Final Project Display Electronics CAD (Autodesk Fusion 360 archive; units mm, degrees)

design "PCB"
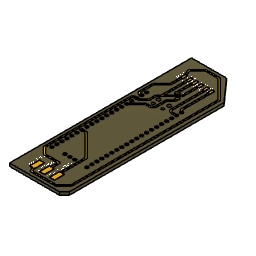
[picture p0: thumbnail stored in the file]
sketch "Outline" plane through (0, 0, 0) normal (0, 0, 1) x axis (1, 0, 0)
  line L1 (35.56, -1.27) -> (10.16, -1.27)
  line L2 (38.1, 1.27) -> (35.56, -1.27)
  line L3 (38.1, 80.01) -> (38.1, 1.27)
  line L4 (27.94, 91.44) -> (38.1, 80.01)
  line L5 (10.16, 91.44) -> (27.94, 91.44)
  line L6 (10.16, -1.27) -> (10.16, 91.44)
canvas "Canvas1" bodies "Board"
canvas "Canvas2" bodies "Board"
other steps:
extrude "Extrude1" sketch "Outline" blind 1.5 bodies "Board"
box_primitive "BoxPrimitive1" DistanceX 4.572 DistanceY 2.159 DistanceZ 0.1 OffsetDistanceX 0 OffsetDistanceY 0
box_primitive "BoxPrimitive1" DistanceX 1.27 DistanceY 2.54 DistanceZ 1.897 OffsetDistanceX 0 OffsetDistanceY 0
box_primitive "BoxPrimitive1" DistanceX 2.54 DistanceY 5.08 DistanceZ 2.4419 OffsetDistanceX 0 OffsetDistanceY 0
pcbextrude "PCBExtrude1"
pcbextrude "PCBExtrude1"
pcbextrude "PCBExtrude1"
box_primitive "BoxPrimitive1" DistanceX 23.9112 DistanceY 52.4397 DistanceZ 0.1 OffsetDistanceX 0 OffsetDistanceY 0
pcbextrude "PCBExtrude2" bodies "CopperHoles"
pcbhole "PCBHole1"
create_component "CreateComponent1"
create_component "CreateComponent2"
create_component "CreateComponent3"
create_component "CreateComponent4"
create_component "CreateComponent1"
as_built_joint "As-built1"
create_component "CreateComponent8"
create_component "CreateComponent9"
create_component "CreateComponent10"
named bodies: "Board", "CopperHoles"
